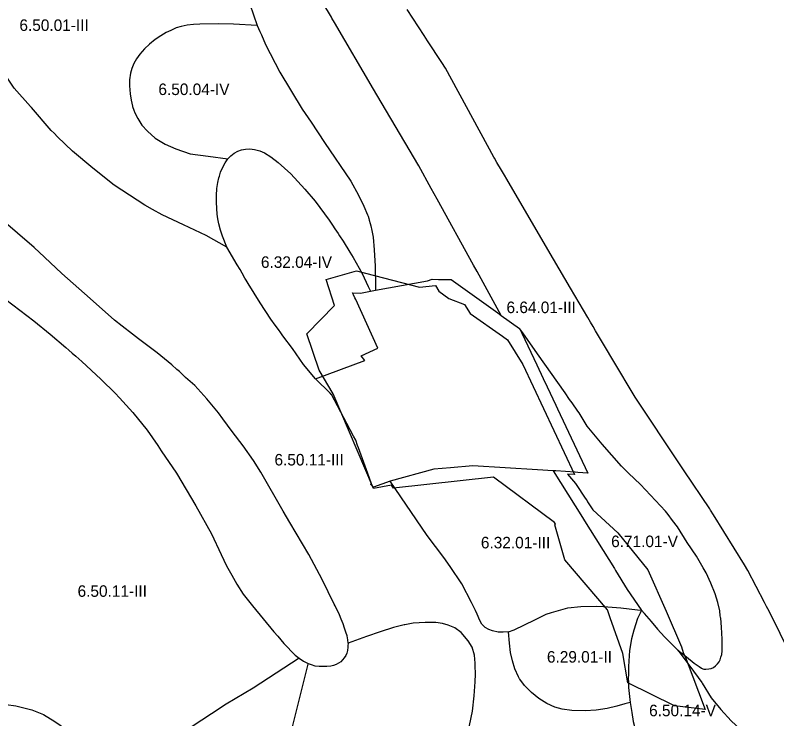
# Model space of a CAD drawing. Extents: x -555156 to -540209, y -1046851 to -1035695.
# Drawn here: x -541802 to -541141, y -1039433 to -1038823 of the extents above; entities that cross this region are included whole.
import ezdxf

# ---------------------------------------------------------------- set-up
doc = ezdxf.new("R2010")
doc.units = 0
for name, color, linetype in [('Vrstva 27', 7, 'Continuous'), ('Vrstva 28', 7, 'Continuous'), ('Vrstva 29', 7, 'Continuous')]:
    doc.layers.add(name, color=color, linetype=linetype)

msp = doc.modelspace()

# ---------------------------------------------------------------- linework, layer by layer
at = {"layer": 'Vrstva 28'}
for points in [[(-541380.04, -1039082.96), (-541381.79, -1039079.78), (-541401.05, -1039044.89), (-541404.1, -1039039.37), (-541435.69, -1038982.14), (-541438.3, -1038977.41), (-541440.84, -1038972.81), (-541451.59, -1038953.35), (-541488.19, -1038891.57), (-541490.98, -1038886.8), (-541524.83, -1038828.9), (-541527.04, -1038825.13), (-541527.53, -1038824.28), (-541564.9, -1038761.93), (-541566.67, -1038758.97), (-541568.59, -1038755.36), (-541581.53, -1038730.99), (-541583.02, -1038728.19), (-541586.54, -1038721.57), (-541599.08, -1038699.34), (-541612.42, -1038677.5)], [(-541598.43, -1038813.06), (-541591.9, -1038831.36)], [(-541126.34, -1039382.65), (-541143.75, -1039347.12), (-541148.83, -1039337.37), (-541149.78, -1039335.55), (-541151.64, -1039331.98), (-541166.17, -1039304.09), (-541169.11, -1039299.34), (-541195.99, -1039255.96), (-541198.44, -1039252), (-541199.14, -1039250.88), (-541221.28, -1039217.78), (-541224.75, -1039212.6), (-541263.98, -1039153.96), (-541272.55, -1039139.51), (-541274.64, -1039135.98), (-541298.19, -1039096.26), (-541300.36, -1039092.6), (-541302.53, -1039088.94), (-541305.01, -1039084.76), (-541320.02, -1039059.45), (-541339.76, -1039025.67), (-541375.39, -1038964.68), (-541377.38, -1038961.27), (-541379.81, -1038957.11), (-541383.84, -1038950.21), (-541386.04, -1038946.44), (-541386.4, -1038945.83), (-541428.49, -1038868.48), (-541431.68, -1038863.62), (-541443.98, -1038844.91), (-541447.04, -1038840.25), (-541461.88, -1038817.68)], [(-541591.9, -1038831.36), (-541612.46, -1038830.28), (-541625.53, -1038830.01), (-541641.66, -1038830.39), (-541647.33, -1038830.69), (-541652.56, -1038831.14), (-541657.94, -1038832.33), (-541662.12, -1038833.53), (-541666.9, -1038835.77), (-541670.93, -1038837.71), (-541675.56, -1038840.55), (-541680.49, -1038843.69), (-541685.42, -1038847.57), (-541689.75, -1038851.76), (-541693.79, -1038856.39), (-541696.62, -1038860.43), (-541699.01, -1038864.46), (-541700.66, -1038868.8), (-541702, -1038872.98), (-541702.75, -1038878.51), (-541702.75, -1038883.89), (-541702.15, -1038890.69), (-541701.4, -1038896.22), (-541700.21, -1038901.45), (-541700.1, -1038901.75), (-541698.95, -1038904.95), (-541698.12, -1038907.28), (-541695.43, -1038912.21), (-541692.14, -1038917.89), (-541687.21, -1038923.27), (-541680.34, -1038929.1), (-541671.83, -1038934.33), (-541662.42, -1038938.51), (-541650.17, -1038942.7), (-541634.34, -1038944.79), (-541617.3, -1038947.16)], [(-541591.9, -1038831.36), (-541589.55, -1038836.65), (-541588.25, -1038839.58), (-541584.58, -1038847.84), (-541572.13, -1038871.92), (-541552.79, -1038904.09), (-541545.2, -1038915.37), (-541533.44, -1038932.86)], [(-541618.18, -1039023.63), (-541636.21, -1039013.69), (-541655.82, -1039004.54), (-541674.38, -1038995.64), (-541682.91, -1038991.02), (-541689.47, -1038987.47), (-541716.14, -1038969.95), (-541734.69, -1038955.3), (-541752.21, -1038940.39), (-541765.14, -1038928), (-541768.25, -1038925.02), (-541770.77, -1038922.61), (-541787.76, -1038902.73), (-541788.67, -1038901.71), (-541802.88, -1038885.77), (-541810.95, -1038873.67), (-541816.47, -1038864.4), (-541820.06, -1038856.78)], [(-541617.3, -1038947.16), (-541614.91, -1038944.68), (-541611.92, -1038942.12), (-541608.85, -1038940.41), (-541605.43, -1038939.3), (-541602.02, -1038938.71), (-541598.26, -1038938.62), (-541594.25, -1038939.05), (-541589.73, -1038940.16), (-541587.71, -1038941.09), (-541585.63, -1038942.04), (-541580.17, -1038945.37), (-541573.6, -1038950.32), (-541562.67, -1038960.14), (-541550.52, -1038973.34), (-541541.71, -1038983.8), (-541529.46, -1039000.24), (-541526.46, -1039004.8), (-541524.52, -1039007.74), (-541521.72, -1039012), (-541520.49, -1039013.87), (-541517.36, -1039018.62), (-541511.5, -1039028.21), (-541508.74, -1039032.74), (-541508.69, -1039032.82), (-541500.93, -1039046.72), (-541495.59, -1039057.92), (-541493.66, -1039061.96)], [(-541533.44, -1038932.86), (-541510.7, -1038966.59), (-541504.06, -1038978.77), (-541499.28, -1038988.19), (-541496.13, -1038995.64), (-541495.55, -1038997.01), (-541495.02, -1038998.96), (-541494.63, -1039000.38), (-541493.85, -1039003.25), (-541493.31, -1039005.23), (-541492.54, -1039009.23), (-541491.37, -1039015.24), (-541490.32, -1039026.15), (-541489.58, -1039040.2), (-541489.2, -1039056.68), (-541489.1, -1039061.14)], [(-541618.18, -1039023.63), (-541622.01, -1039014.16), (-541623.66, -1039009.08), (-541625.06, -1039003.59), (-541626, -1038999.15), (-541626.69, -1038995.22), (-541627.03, -1038990.1), (-541627.28, -1038984.8), (-541627.2, -1038978.99), (-541626.86, -1038973.02), (-541626.09, -1038967.55), (-541625.23, -1038963.64), (-541624.73, -1038962.1), (-541623.61, -1038958.69), (-541621.56, -1038953.91), (-541619.6, -1038950.66), (-541617.3, -1038947.16)], [(-541513.07, -1039367.3), (-541513.33, -1039364.49), (-541513.93, -1039360.99), (-541514.87, -1039357.83), (-541516.06, -1039354.15), (-541517.26, -1039350.57), (-541518.96, -1039346.38), (-541520.41, -1039342.8), (-541524.37, -1039335.01), (-541525.11, -1039333.56), (-541535.56, -1039312.11), (-541547.06, -1039290.4), (-541563.51, -1039262.52), (-541569.28, -1039252.74), (-541588.89, -1039219), (-541595.21, -1039208.89), (-541604.1, -1039196.07), (-541613.51, -1039183.78), (-541621.83, -1039172.56), (-541625.53, -1039167.56), (-541635.72, -1039155.27), (-541645.92, -1039143.76), (-541654.02, -1039136.7), (-541656.76, -1039134.2), (-541659.44, -1039131.75), (-541661.63, -1039129.75), (-541666.05, -1039125.72), (-541678.59, -1039115.52), (-541694.81, -1039103.34), (-541697.41, -1039101.39), (-541702.84, -1039097.12), (-541706.43, -1039094.3), (-541709.02, -1039092.27), (-541715.71, -1039087.01), (-541736.85, -1039068.44), (-541761.42, -1039046.47), (-541776.5, -1039032.37), (-541785.47, -1039023.98), (-541814.49, -1038999.13)], [(-541541.26, -1039138), (-541551.62, -1039125.55), (-541561.33, -1039111.8), (-541569.54, -1039100.74), (-541571.53, -1039097.95), (-541573.41, -1039095.31), (-541576.26, -1039091.29), (-541579.96, -1039086.09), (-541589.37, -1039071.97), (-541599.83, -1039055.23), (-541601.42, -1039052.49), (-541602.56, -1039050.53), (-541605.02, -1039046.29), (-541606.77, -1039043.27), (-541609.24, -1039039.02), (-541618.18, -1039023.63)], [(-541489.1, -1039061.14), (-541444.15, -1039053.04), (-541440, -1039051.62), (-541434.44, -1039051.73), (-541423.66, -1039051.94)], [(-541423.66, -1039051.94), (-541383.04, -1039080.83), (-541380.04, -1039082.96)], [(-541541.26, -1039138), (-541498.56, -1039122.21), (-541501.66, -1039118.05), (-541487.16, -1039111.43), (-541506.42, -1039069.22), (-541507.05, -1039067.84), (-541508.34, -1039065.03), (-541509.11, -1039063.35), (-541502.35, -1039063.53), (-541493.66, -1039061.96)], [(-541493.66, -1039061.96), (-541489.1, -1039061.14)], [(-541810.11, -1039069.17), (-541785.8, -1039087.74), (-541771.57, -1039099.17), (-541757.98, -1039110.94), (-541755.48, -1039113.11), (-541752.6, -1039115.61), (-541749.43, -1039118.37), (-541744.13, -1039122.97), (-541727.66, -1039138.14), (-541714.99, -1039150.81), (-541713.54, -1039152.26), (-541713.11, -1039152.73), (-541711.41, -1039154.59), (-541699.95, -1039167.17), (-541687.4, -1039182.6), (-541678.28, -1039195.81), (-541675.12, -1039200.38), (-541662.05, -1039219.73), (-541645.06, -1039248.24), (-541631.47, -1039272.57), (-541623.2, -1039290.46), (-541618.66, -1039300.29), (-541613.96, -1039308.4), (-541609.48, -1039316.02), (-541603.95, -1039324.84), (-541596.04, -1039335), (-541586.78, -1039346.21), (-541577.37, -1039357.42), (-541574.04, -1039361.27), (-541568.7, -1039367.43), (-541558.99, -1039377.6), (-541555.58, -1039380.37)], [(-541380.04, -1039082.96), (-541364.17, -1039094.25)], [(-541364.17, -1039094.25), (-541362.24, -1039098.34), (-541349.25, -1039125.81), (-541343.67, -1039137.6), (-541340.15, -1039145.06), (-541332.77, -1039160.68), (-541331.18, -1039164.03), (-541304.84, -1039219.76), (-541313.64, -1039219.14), (-541315.92, -1039218.98), (-541332.77, -1039217.83), (-541335.04, -1039217.69)], [(-541271.96, -1039217.53), (-541275.86, -1039213.87), (-541292.59, -1039194.78), (-541305.4, -1039179.09), (-541312.58, -1039167.5), (-541313.51, -1039166.01), (-541318.52, -1039158.92), (-541320.73, -1039155.78), (-541324.68, -1039150.19), (-541348.63, -1039116.27), (-541361.38, -1039098.2), (-541364.17, -1039094.25)], [(-541491.51, -1039231.4), (-541493.71, -1039229.4), (-541492.73, -1039229.04), (-541495.98, -1039220.01), (-541503.95, -1039197.87), (-541504.72, -1039195.73), (-541506.33, -1039191.24), (-541508.19, -1039187.74), (-541514.01, -1039176.75), (-541527.51, -1039151.61), (-541527.59, -1039151.46), (-541528.62, -1039150.45), (-541541.26, -1039138)], [(-541335.04, -1039217.69), (-541348.68, -1039216.83), (-541404.66, -1039213.31), (-541424.23, -1039215.09), (-541438.48, -1039216.39), (-541476.39, -1039226.8)], [(-541335.04, -1039217.69), (-541309.57, -1039258.36), (-541307.82, -1039261.15), (-541281.93, -1039302.51), (-541280.83, -1039304.27), (-541270.82, -1039320.71)], [(-541226.84, -1039373.37), (-541219.44, -1039379.19), (-541212.6, -1039384.57), (-541208.41, -1039387.64), (-541206.31, -1039388.96), (-541205.1, -1039389.44), (-541204.21, -1039389.79), (-541202.51, -1039389.93), (-541200.07, -1039389.64), (-541198.02, -1039389.1), (-541195.97, -1039388.23), (-541194.07, -1039386.96), (-541192.46, -1039385.3), (-541191.09, -1039383.54), (-541190.21, -1039381.59), (-541189.43, -1039379.54), (-541188.8, -1039376.95), (-541188.41, -1039373.98), (-541188.31, -1039369.19), (-541188.41, -1039363.83), (-541188.91, -1039353.48), (-541189.63, -1039345.58), (-541189.68, -1039345.03), (-541189.97, -1039343.14), (-541190.5, -1039339.49), (-541190.53, -1039339.31), (-541192.07, -1039332.05), (-541194.46, -1039324.53), (-541198.13, -1039315.22), (-541202.35, -1039306.19), (-541204.86, -1039301.89), (-541210.71, -1039291.84), (-541218.63, -1039280.03), (-541227.14, -1039266.43), (-541231.36, -1039260.81), (-541235.31, -1039255.55), (-541237.45, -1039252.69), (-541259.14, -1039229.56), (-541269.57, -1039219.77), (-541271.96, -1039217.53)], [(-541476.39, -1039226.8), (-541491.03, -1039231.83), (-541491.51, -1039231.4)], [(-541373.7, -1039357.33), (-541378.3, -1039357.85), (-541382.91, -1039357.59), (-541387.61, -1039356.65), (-541391.02, -1039355.37), (-541393.92, -1039353.66), (-541396.83, -1039350.67), (-541398.7, -1039347.68), (-541401.09, -1039342.06), (-541402.57, -1039339.02), (-541406.06, -1039331.86), (-541414.42, -1039315.9), (-541424.36, -1039300.73), (-541430.07, -1039293.04), (-541444.42, -1039273.73), (-541476.39, -1039226.8)], [(-541270.82, -1039320.71), (-541258.65, -1039338.31), (-541258.43, -1039338.64)], [(-541373.7, -1039357.33), (-541368.92, -1039355.71), (-541351.09, -1039347.14), (-541341.23, -1039342.21), (-541336.5, -1039340.66), (-541332.57, -1039339.37), (-541322.26, -1039336.68), (-541311.06, -1039335.34), (-541297.61, -1039335.04), (-541291.43, -1039335.47), (-541276.25, -1039336.53), (-541261.91, -1039338.23), (-541258.43, -1039338.64)], [(-541258.43, -1039338.64), (-541259.68, -1039341.35), (-541261.79, -1039345.95), (-541265.07, -1039356.11), (-541267.02, -1039363.44), (-541268.66, -1039373.75), (-541269.56, -1039387.5), (-541269.61, -1039389.43), (-541269.72, -1039393.21), (-541269.76, -1039394.49), (-541269.85, -1039397.81), (-541269.79, -1039401.12), (-541269.72, -1039404.47), (-541269.7, -1039405.58), (-541268.33, -1039418.65)], [(-541258.43, -1039338.64), (-541256.11, -1039341.37), (-541256.05, -1039341.44), (-541250.06, -1039348.5), (-541244.53, -1039355.08), (-541238.36, -1039361.78), (-541237.51, -1039362.7), (-541236.12, -1039364.09), (-541226.84, -1039373.37)], [(-541402.84, -1039384.72), (-541403.44, -1039377.55), (-541405.38, -1039370.82), (-541408.82, -1039365.14), (-541414.94, -1039358.04), (-541420.47, -1039354.01), (-541426.15, -1039351.62), (-541431.22, -1039350.27), (-541436.9, -1039349.38), (-541446.01, -1039349.23), (-541456.47, -1039349.97), (-541463.72, -1039351.37), (-541464.23, -1039351.47), (-541473.5, -1039353.71), (-541485.26, -1039357.45), (-541497.06, -1039361.48), (-541513.07, -1039367.3)], [(-541297.61, -1039425.37), (-541307.32, -1039425.97), (-541318.82, -1039425.67), (-541327.18, -1039424.63), (-541333.46, -1039422.68), (-541340.48, -1039419.69), (-541347.5, -1039415.21), (-541353.77, -1039409.98), (-541359.9, -1039403.85), (-541364.06, -1039398.54), (-541364.23, -1039398.32), (-541365.17, -1039396.33), (-541368.41, -1039389.51), (-541370.35, -1039382.48), (-541371.99, -1039375.31), (-541372.89, -1039367.24), (-541373.7, -1039357.33)], [(-541513.07, -1039367.3), (-541513.19, -1039369.69), (-541513.24, -1039370.81), (-541513.59, -1039373.54), (-541514.18, -1039375.84), (-541515.12, -1039377.98), (-541516.4, -1039380.03), (-541517.85, -1039381.74), (-541519.39, -1039383.36), (-541521.27, -1039384.73), (-541523.23, -1039385.75), (-541525.71, -1039386.61), (-541528.1, -1039387.2), (-541531.6, -1039387.54), (-541534.5, -1039387.54), (-541538.17, -1039387.46), (-541541.5, -1039387.12), (-541544.82, -1039386.18), (-541547.28, -1039385.13), (-541547.81, -1039384.9)], [(-541226.84, -1039373.37), (-541216.55, -1039387.29), (-541206.1, -1039401.43), (-541205.63, -1039402.06), (-541198.01, -1039414.62), (-541189.65, -1039424.78), (-541180.54, -1039434.5), (-541172.6, -1039442.27), (-541171.51, -1039443.23), (-541164.41, -1039449.45), (-541162.43, -1039450.83), (-541158.18, -1039453.8), (-541157.07, -1039454.57), (-541152.85, -1039456.85)], [(-541555.58, -1039380.37), (-541595.29, -1039406.4), (-541618.82, -1039420.26), (-541631.69, -1039428.7), (-541648.36, -1039439.62), (-541693.58, -1039475.97), (-541740.02, -1039515.23)], [(-541555.58, -1039380.37), (-541551.82, -1039382.85), (-541547.81, -1039384.9)], [(-541547.81, -1039384.9), (-541547.96, -1039385.48), (-541567.16, -1039461.82), (-541567.85, -1039464.55), (-541581.29, -1039518.01), (-541585.95, -1039534.35), (-541587.08, -1039538.29), (-541597.09, -1039573.37), (-541603.21, -1039592.5), (-541609.03, -1039604.31), (-541614.71, -1039613.28), (-541623.67, -1039623.89), (-541629.05, -1039629.27), (-541631.58, -1039631.12)], [(-541413.02, -1039465.01), (-541405.16, -1039426.38), (-541403.67, -1039412.93), (-541402.86, -1039400.83), (-541402.72, -1039398.71), (-541402.55, -1039396.23), (-541402.84, -1039384.72)], [(-541818.43, -1039419.31), (-541801.44, -1039421.66), (-541787.59, -1039425.06), (-541777.39, -1039429.25), (-541767.46, -1039435.26), (-541762.99, -1039438.49), (-541758.05, -1039442.06), (-541749.68, -1039450.95), (-541743.15, -1039462.2), (-541742.05, -1039465.18), (-541739.49, -1039472.14), (-541738.18, -1039484.43), (-541737.66, -1039499.34), (-541738.38, -1039507.31), (-541740.02, -1039515.23)], [(-541268.33, -1039418.65), (-541272.96, -1039419.99), (-541279.83, -1039421.94), (-541288.2, -1039423.88), (-541297.61, -1039425.37)], [(-541268.33, -1039418.65), (-541266.89, -1039427.48), (-541265.55, -1039435.11), (-541263.91, -1039441.83), (-541261.67, -1039448.26), (-541258.83, -1039455.28), (-541257.98, -1039456.69), (-541254.65, -1039462.16), (-541249.72, -1039468.14), (-541243.74, -1039473.07), (-541237.17, -1039476.35), (-541230.15, -1039479.05), (-541221.19, -1039480.84), (-541212.08, -1039481.14), (-541201.62, -1039480.69)]]:
    msp.add_lwpolyline(points, dxfattribs=at)
at = {"layer": 'Vrstva 29'}
msp.add_lwpolyline([(-541475.311963, -1039230.224421), (-541490.9, -1039233.13), (-541526.000329, -1039151.063274), (-541538.247006, -1039130.395992), (-541548.843001, -1039098.965005), (-541524.685004, -1039074.490993), (-541531.978992, -1039051.890007), (-541505.732006, -1039044.281993), (-541451.085722, -1039058.587763), (-541437.28, -1039057.08), (-541434.14, -1039062.06), (-541425.447917, -1039068.222156), (-541411.922007, -1039073.365004), (-541406.997615, -1039081.302294), (-541379.1, -1039101.08), (-541374.79, -1039104.13), (-541361.29, -1039125.46), (-541316.4, -1039220.98), (-541322.470853, -1039220.732449), (-541315.735001, -1039228.771006), (-541306.758921, -1039242.378422), (-541306.46, -1039242.13), (-541305.316151, -1039244.56561), (-541300.623323, -1039251.679769), (-541278.86, -1039271.44), (-541253, -1039303.68), (-541236.9, -1039339.48), (-541223.62, -1039370.35), (-541222.236693, -1039375.382917), (-541219.691995, -1039381.091002), (-541203.127994, -1039424.738007), (-541229.881004, -1039421.548006), (-541270.261994, -1039401.648992), (-541274.711218, -1039376.151679), (-541285.56, -1039345.34), (-541287.81, -1039338.25), (-541324.81, -1039295.07), (-541333.63, -1039264.71), (-541332.938892, -1039264.135645), (-541333.844999, -1039262.658994), (-541386.765001, -1039223.368002), (-541473.626, -1039232.695004), (-541475.311963, -1039230.224421)], dxfattribs=at)

# ---------------------------------------------------------------- texts
at = {"layer": 'Vrstva 27'}
for s, p in [('6.50.01-III', (-541798.276548, -1038836.22)), ('6.50.04-IV', (-541677.637119, -1038891.82)), ('6.32.04-IV', (-541588.677119, -1039041.74)), ('6.64.01-III', (-541375.536548, -1039080.98)), ('6.50.11-III', (-541576.916548, -1039213.14)), ('6.32.01-III', (-541397.776548, -1039285.03)), ('6.71.01-V', (-541284.721006, -1039283.95)), ('6.50.11-III', (-541747.786548, -1039327.07)), ('6.29.01-II', (-541340.470313, -1039384.13)), ('6.50.14-V', (-541251.780884, -1039430.66))]:
    msp.add_text(s, height=10, dxfattribs=at).set_placement(p)

doc.saveas('drawing.dxf')
